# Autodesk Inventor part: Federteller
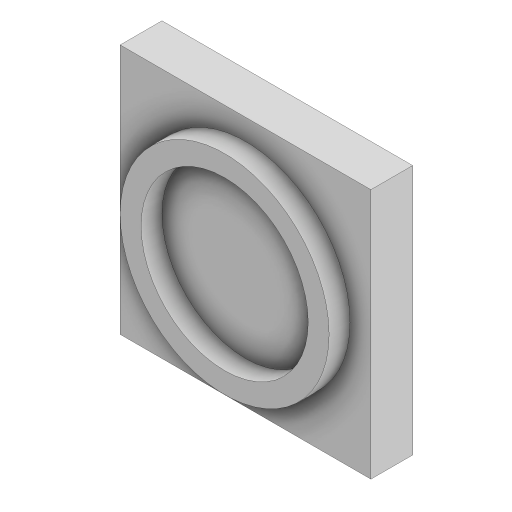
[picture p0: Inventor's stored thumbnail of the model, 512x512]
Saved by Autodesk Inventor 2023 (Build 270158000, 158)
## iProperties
Created: 2023-02
Part Number: Federteller
Material: Generisch
Document SubType Name: Modeling
Designer: Nicole Höfler
Density: 1 g/cm^3
Appearance: Vorgabe
Author: Nicole Höfler
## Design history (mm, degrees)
sketch "Skizze1"
  geometry: L1 (-6, -6)-(6, -6); L2 (6, -6)-(6, 6); L3 (6, 6)-(-6, 6); L4 (-6, 6)-(-6, -6); L5 (-6, -6)-(6, 6); L6 (6, -6)-(-6, 6); 1 further point
  constraints: 12 end point, 2 midpoint, 2 parallel, 1 horizontal, 1 perpendicular
  dimensions: "d0" = 12 distance of L3.end L2.end; "d1" = 12 distance of L2.end L1.end
extrude "Extrusion1" new body sketch "Skizze1" distance "d2" = 2; taper "d3" = 0 deg
sketch "Skizze2"
  geometry: C1 r 4 at (0, 0); C2 r 5 at (0, 0); 1 further point
  constraints: 2 centre point, 2 coincident
  dimensions: "d4" = 8 diameter of C1; "d5" = 10 diameter of C2
extrude "Extrusion2" join sketch "Skizze2" distance "d6" = 1; taper "d7" = 0 deg
node "Volumenkörper1"
